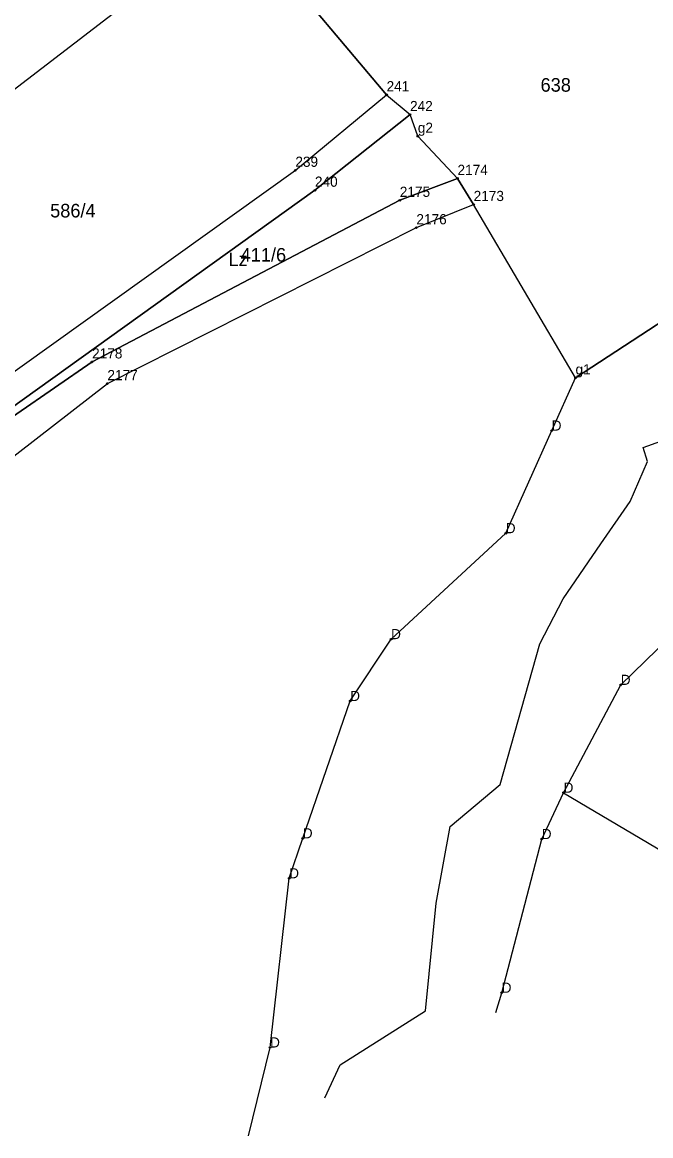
# Model space of a CAD drawing. Extents: x 7467189 to 7469366, y 5491487 to 5492734.
# Drawn here: x 7469084.3 to 7469153.7, y 5491520.7 to 5491643.7 of the extents above; entities that cross this region are included whole.
import ezdxf

# ---------------------------------------------------------------- set-up
doc = ezdxf.new("R2010")
doc.units = 0
for name, color, linetype in [('203-punkt graniczny', 7, 'Continuous'), ('203-punkt graniczny-Atr103', 7, 'Continuous'), ('210-oznaczenie konturu użytku gruntowego', 7, 'Continuous'), ('211-numer działki ewidencyjnej', 7, 'Continuous'), ('217-kontur klasyfikacyjny', 7, 'Continuous'), ('218-kontur użytku gruntowego', 7, 'Continuous'), ('219-działka ewidencyjna', 7, 'Continuous')]:
    doc.layers.add(name, color=color, linetype=linetype)

# ---------------------------------------------------------------- blocks, each defined once
blk = doc.blocks.new('203')
blk.add_circle((0, 0), 0.09)

msp = doc.modelspace()

# ---------------------------------------------------------------- linework, layer by layer
at = {"layer": '217-kontur klasyfikacyjny'}
for points in [[(7469124.56, 5491635.75), (7469111.27, 5491651.54)], [(7469114.49, 5491627.4), (7469124.56, 5491635.75)], [(7469074.31, 5491598.67), (7469114.49, 5491627.4)]]:
    msp.add_lwpolyline(points, dxfattribs=at)
at = {"layer": '218-kontur użytku gruntowego'}
for points in [[(7469124.56, 5491635.75), (7469111.27, 5491651.54)], [(7469114.49, 5491627.4), (7469124.56, 5491635.75)], [(7469127.15, 5491633.56), (7469116.65, 5491625.2)], [(7469128.01, 5491631.16), (7469127.15, 5491633.56)], [(7469132.39, 5491626.5), (7469128.01, 5491631.16)], [(7469074.31, 5491598.67), (7469114.49, 5491627.4)], [(7469132.39, 5491626.5), (7469126.02, 5491624.08)], [(7469134.17, 5491623.62), (7469132.39, 5491626.5)], [(7469116.65, 5491625.2), (7469076.34, 5491596.28)], [(7469126.02, 5491624.08), (7469092.05, 5491606.23)], [(7469127.85, 5491621.06), (7469134.17, 5491623.62)], [(7469145.42, 5491604.47), (7469134.17, 5491623.62)], [(7469093.74, 5491603.84), (7469127.85, 5491621.06)], [(7469163.35, 5491616.17), (7469145.42, 5491604.47)], [(7469092.05, 5491606.23), (7469075.39, 5491594.74)], [(7469142.79, 5491598.64), (7469145.42, 5491604.47)], [(7469152.87, 5491596.77), (7469175.05, 5491604.74)], [(7469077.95, 5491591.62), (7469093.74, 5491603.84)], [(7469137.72, 5491587.3), (7469142.79, 5491598.64)], [(7469153.38, 5491595.21), (7469152.87, 5491596.77)], [(7469151.44, 5491590.81), (7469153.38, 5491595.21)], [(7469148.21, 5491586.15), (7469151.44, 5491590.81)], [(7469125.06, 5491575.6), (7469137.72, 5491587.3)], [(7469144.06, 5491580.06), (7469148.21, 5491586.15)], [(7469141.49, 5491575.07), (7469144.06, 5491580.06)], [(7469120.54, 5491568.77), (7469125.06, 5491575.6)], [(7469137.09, 5491559.53), (7469141.49, 5491575.07)], [(7469115.31, 5491553.6), (7469120.54, 5491568.77)], [(7469131.58, 5491554.89), (7469137.09, 5491559.53)], [(7469130.03, 5491546.44), (7469131.58, 5491554.89)], [(7469113.81, 5491549.18), (7469115.31, 5491553.6)], [(7469111.7, 5491530.49), (7469113.81, 5491549.18)], [(7469128.84, 5491534.53), (7469130.03, 5491546.44)], [(7469119.44, 5491528.58), (7469128.84, 5491534.53)], [(7469109.3, 5491520.74), (7469111.7, 5491530.49)], [(7469117.73, 5491524.94), (7469119.44, 5491528.58)]]:
    msp.add_lwpolyline(points, dxfattribs=at)
at = {"layer": '219-działka ewidencyjna'}
for points in [[(7469108.36, 5491655.46), (7469050.51, 5491611.01)], [(7469111.27, 5491651.54), (7469124.56, 5491635.75)], [(7469114.49, 5491627.4), (7469124.56, 5491635.75)], [(7469124.56, 5491635.75), (7469127.15, 5491633.56)], [(7469116.65, 5491625.2), (7469127.15, 5491633.56)], [(7469128.01, 5491631.16), (7469127.15, 5491633.56)], [(7469128.01, 5491631.16), (7469132.39, 5491626.5)], [(7469074.31, 5491598.67), (7469114.49, 5491627.4)], [(7469126.02, 5491624.08), (7469132.39, 5491626.5)], [(7469132.39, 5491626.5), (7469134.17, 5491623.62)], [(7469076.34, 5491596.28), (7469116.65, 5491625.2)], [(7469092.05, 5491606.23), (7469126.02, 5491624.08)], [(7469127.85, 5491621.06), (7469134.17, 5491623.62)], [(7469145.42, 5491604.47), (7469134.17, 5491623.62)], [(7469093.74, 5491603.84), (7469127.85, 5491621.06)], [(7469145.42, 5491604.47), (7469163.35, 5491616.17)], [(7469075.39, 5491594.74), (7469092.05, 5491606.23)], [(7469142.79, 5491598.64), (7469145.42, 5491604.47)], [(7469077.95, 5491591.62), (7469093.74, 5491603.84)], [(7469137.72, 5491587.3), (7469142.79, 5491598.64)], [(7469125.06, 5491575.6), (7469137.72, 5491587.3)], [(7469150.41, 5491570.55), (7469162.5, 5491582.3)], [(7469120.54, 5491568.77), (7469125.06, 5491575.6)], [(7469144.1, 5491558.64), (7469150.41, 5491570.55)], [(7469115.31, 5491553.6), (7469120.54, 5491568.77)], [(7469141.69, 5491553.52), (7469144.1, 5491558.64)], [(7469144.1, 5491558.64), (7469159.4, 5491549.57)], [(7469113.81, 5491549.18), (7469115.31, 5491553.6)], [(7469137.27, 5491536.54), (7469141.69, 5491553.52)], [(7469111.7, 5491530.49), (7469113.81, 5491549.18)], [(7469136.62, 5491534.34), (7469137.27, 5491536.54)], [(7469109.3, 5491520.74), (7469111.7, 5491530.49)]]:
    msp.add_lwpolyline(points, dxfattribs=at)

# ---------------------------------------------------------------- block references
at = {"layer": '203-punkt graniczny'}
for p in [(7469124.56, 5491635.75), (7469127.15, 5491633.56), (7469128.01, 5491631.16), (7469114.49, 5491627.4), (7469132.39, 5491626.5), (7469116.65, 5491625.2), (7469126.02, 5491624.08), (7469134.17, 5491623.62), (7469127.85, 5491621.06), (7469092.05, 5491606.23), (7469145.42, 5491604.47), (7469093.74, 5491603.84), (7469142.79, 5491598.64), (7469137.72, 5491587.3), (7469125.06, 5491575.6), (7469150.41, 5491570.55), (7469120.54, 5491568.77), (7469144.1, 5491558.64), (7469115.31, 5491553.6), (7469141.69, 5491553.52), (7469113.81, 5491549.18), (7469137.27, 5491536.54), (7469111.7, 5491530.49)]:
    msp.add_blockref('203', p, dxfattribs=at)

# ---------------------------------------------------------------- texts
at = {"layer": '203-punkt graniczny-Atr103'}
for s, height, p in [('241', 1.125, (7469124.56, 5491636.12)), ('242', 1.125, (7469127.15, 5491633.93)), ('g2', 1.125, (7469128.01, 5491631.54)), ('239', 1.125, (7469114.49, 5491627.78)), ('2174', 1.125, (7469132.39, 5491626.88)), ('240', 1.125, (7469116.65, 5491625.58)), ('2175', 1.125, (7469126.02, 5491624.46)), ('2173', 1.125, (7469134.17, 5491624)), ('2176', 1.125, (7469127.85, 5491621.43)), ('2178', 1.125, (7469092.05, 5491606.61)), ('g1', 1.125, (7469145.42, 5491604.85)), ('2177', 1.125, (7469093.74, 5491604.21)), ('D', 1.12, (7469142.79, 5491598.64)), ('D', 1.12, (7469137.72, 5491587.3)), ('D', 1.12, (7469125.06, 5491575.6)), ('D', 1.12, (7469150.41, 5491570.55)), ('D', 1.12, (7469120.54, 5491568.77)), ('D', 1.12, (7469144.1, 5491558.64)), ('D', 1.12, (7469115.31, 5491553.6)), ('D', 1.12, (7469141.69, 5491553.52)), ('D', 1.12, (7469113.81, 5491549.18)), ('D', 1.12, (7469137.27, 5491536.54)), ('D', 1.12, (7469111.7, 5491530.49))]:
    msp.add_text(s, height=height, dxfattribs=at).set_placement(p)
at = {"layer": '210-oznaczenie konturu użytku gruntowego'}
msp.add_text('Lz', height=1.5, dxfattribs=at).set_placement((7469107.1, 5491616.81))
at = {"layer": '211-numer działki ewidencyjnej'}
for s, p in [('638', (7469141.56, 5491636.08)), ('586/4', (7469087.42, 5491622.19)), ('411/6', (7469108.45, 5491617.31))]:
    msp.add_text(s, height=1.5, dxfattribs=at).set_placement(p)

doc.saveas('drawing.dxf')
